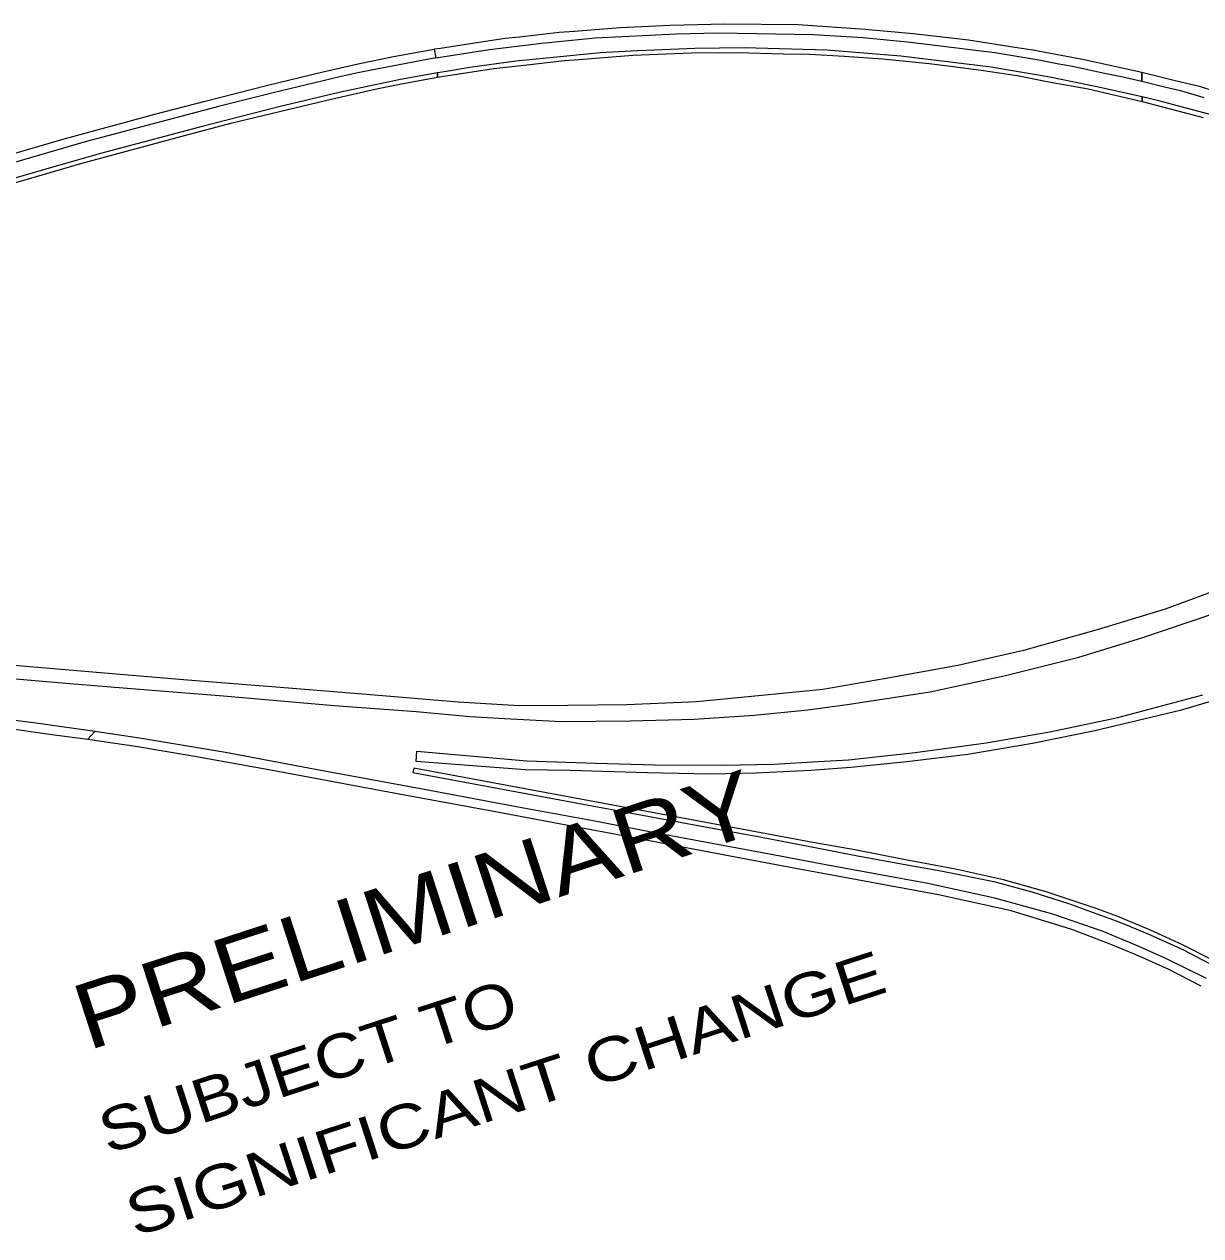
# Model space of a CAD drawing. Extents: x 2355803 to 2371254, y 6970215 to 6985302.
# Drawn here: x 2362590 to 2363679, y 6977121 to 6978242 of the extents above; entities that cross this region are included whole.
import ezdxf

# ---------------------------------------------------------------- set-up
doc = ezdxf.new("R2010")
doc.units = 0
doc.header["$LTSCALE"] = 7.1
doc.layers.add('12', color=7, linetype='Continuous', lineweight=13)
doc.layers.add('5', color=7, linetype='Continuous', lineweight=13)

msp = doc.modelspace()

# ---------------------------------------------------------------- linework, layer by layer
at = {"layer": '12'}
for points in [[(2363624.629, 6978197.498), (2363571.392, 6978209.381), (2363523.829, 6978218.134), (2363507.182, 6978220.687), (2363464.371, 6978227.436), (2363413.032, 6978233.308), (2363368.628, 6978237.458), (2363306.42, 6978241.484), (2363238.311, 6978242.189), (2363187.974, 6978241.153), (2363141.829, 6978238.976), (2363099.505, 6978235.519), (2363085.292, 6978234.446), (2363048.489, 6978230.239), (2363035.277, 6978228.833), (2363009.086, 6978225.094), (2362975.34, 6978219.735), (2362969.629, 6978218.966), (2362971.1, 6978211.141), (2363020.701, 6978218.89), (2363069.298, 6978224.596), (2363118.514, 6978229.587), (2363193.664, 6978233.202), (2363232.268, 6978234.188), (2363268.182, 6978233.646), (2363320.589, 6978232.565), (2363366.688, 6978229.909), (2363410.563, 6978225.707), (2363488.545, 6978215.942), (2363529.465, 6978209.184), (2363546.254, 6978205.766), (2363560.48, 6978203.366), (2363590.269, 6978197.014), (2363607.042, 6978193.523), (2363624.805, 6978189.625)], [(2363624.976, 6978174.991), (2363582.975, 6978184.382), (2363539.557, 6978193.128), (2363485.231, 6978202.456), (2363401.593, 6978212.54), (2363332.987, 6978218.305), (2363256.709, 6978220.424), (2363211.018, 6978219.828), (2363157.725, 6978217.709), (2363123.334, 6978215.629), (2363089.286, 6978212.47), (2363045.305, 6978207.864), (2363002.644, 6978202.096), (2362980.78, 6978198.465), (2362972.709, 6978197.189), (2362972.69, 6978193.077), (2362994.479, 6978196.708), (2363024.697, 6978201.2), (2363058.025, 6978205.058), (2363090.364, 6978208.662), (2363103.38, 6978209.64), (2363153.423, 6978213.644), (2363207.777, 6978215.725), (2363250.035, 6978216.008), (2363293.01, 6978214.936), (2363317.481, 6978214.624), (2363349.278, 6978212.61), (2363384.641, 6978210.293), (2363427.888, 6978205.897), (2363450.034, 6978203.018), (2363475.958, 6978199.616), (2363509.271, 6978194.596), (2363540.103, 6978188.672), (2363574.924, 6978182.425), (2363624.928, 6978170.71)]]:
    msp.add_lwpolyline(points, close=True, dxfattribs=at)
for points in [[(2362564.258, 6978117.891), (2362624.835, 6978135.481), (2362710.835, 6978159.048), (2362757.488, 6978171.135), (2362815.524, 6978185.767), (2362865.278, 6978197.781), (2362900.446, 6978205.836), (2362931.776, 6978212.169), (2362969.629, 6978218.966), (2362971.1, 6978211.141), (2362916.27, 6978200.68), (2362897.259, 6978196.992), (2362882.165, 6978193.498), (2362820.575, 6978178.838), (2362771.184, 6978166.213), (2362646.483, 6978133.232), (2362569.269, 6978110.865)], [(2362565.763, 6978091.095), (2362608.652, 6978103.551), (2362642.395, 6978113.398), (2362738.265, 6978139.302), (2362782.543, 6978150.9), (2362868.919, 6978171.641), (2362916.205, 6978182.531), (2362939.372, 6978186.991), (2362972.69, 6978193.077), (2362972.709, 6978197.189), (2362938.326, 6978191.032), (2362903.087, 6978183.677), (2362878.864, 6978178.297), (2362849.289, 6978171.205), (2362825.83, 6978165.795), (2362754.696, 6978147.593), (2362660.76, 6978122.394), (2362609.956, 6978108.092), (2362557.445, 6978092.824)], [(2363692.731, 6978179.876), (2363679.232, 6978184.094), (2363655.675, 6978189.842), (2363624.629, 6978197.498), (2363624.805, 6978189.625), (2363645.8, 6978184.328), (2363660.668, 6978180.746), (2363682.194, 6978174.357)], [(2363695.886, 6978156.339), (2363639.328, 6978171.62), (2363624.976, 6978174.991), (2363624.928, 6978170.71), (2363681.652, 6978155.806)], [(2363706.611, 6977722.987), (2363646.266, 6977700.933), (2363583.373, 6977681.803), (2363515.068, 6977662.545), (2363454.374, 6977648.76), (2363386.068, 6977636.231), (2363329.492, 6977626.378), (2363272.851, 6977620.926), (2363212.342, 6977615.191), (2363147.995, 6977612.285), (2363093.333, 6977611.645), (2363048.232, 6977611.447), (2362991.618, 6977614.583), (2362910.563, 6977621.436), (2362826.863, 6977628.292), (2362741.205, 6977635.148), (2362660.639, 6977642.001), (2362562.255, 6977650.326)], [(2362542.394, 6977639.613), (2362632.263, 6977632.071), (2362704.56, 6977626.146), (2362774.426, 6977620.591), (2362876.969, 6977611.626), (2362952.771, 6977606.029), (2363003.001, 6977601.385), (2363034.639, 6977599.482), (2363087.555, 6977596.953), (2363150.94, 6977597.446), (2363210.167, 6977598.916), (2363265.967, 6977602.833), (2363315.403, 6977607.73), (2363351.794, 6977612.629), (2363428.857, 6977624.251), (2363497.42, 6977639.083), (2363566.446, 6977656.232), (2363624.817, 6977674.308), (2363689.673, 6977696.092)], [(2363725.621, 6977626.57), (2363660.301, 6977607.104), (2363581.27, 6977588.099), (2363523.363, 6977576.511), (2363463.602, 6977566.315), (2363407.084, 6977559.362), (2363355.228, 6977554.22), (2363318.389, 6977551.409), (2363267.813, 6977548.91), (2363225.355, 6977547.973), (2363166.662, 6977549.222), (2363095.169, 6977551.409), (2363053.912, 6977552.19), (2362952.814, 6977559.66), (2362953.59, 6977569.421), (2363055.288, 6977560.452), (2363119.208, 6977558.28), (2363173.842, 6977556.719), (2363237.218, 6977556.406), (2363284.048, 6977557.343), (2363324.945, 6977559.842), (2363353.043, 6977561.404), (2363414.959, 6977568.169), (2363480.742, 6977576.975), (2363539.577, 6977587.172), (2363602.58, 6977600.613), (2363681.148, 6977621.472)], [(2362572.625, 6977591.105), (2362615.485, 6977584.956), (2362648.934, 6977580.42), (2362655.255, 6977587.643), (2362603.182, 6977594.831), (2362545.384, 6977602.496)], [(2363684.669, 6977358.895), (2363647.003, 6977377.405), (2363621.355, 6977388.894), (2363588.891, 6977402.452), (2363542.429, 6977418.548), (2363488.76, 6977433.337), (2363426.492, 6977446.809), (2363332.046, 6977464.244), (2363285.056, 6977473.059), (2363175.414, 6977493.627), (2363116.677, 6977504.89), (2363055.74, 6977516.15), (2362955.397, 6977534.759), (2362859.658, 6977552.386), (2362776.447, 6977568.057), (2362696.86, 6977581.276), (2362655.255, 6977587.643), (2362648.934, 6977580.42), (2362692.945, 6977573.931), (2362746.1, 6977565.119), (2362820.01, 6977551.896), (2362937.287, 6977529.862), (2363022.945, 6977514.191), (2363085.351, 6977502.442), (2363152.898, 6977489.709), (2363211, 6977478.622), (2363297.665, 6977462.225), (2363436.433, 6977436.862), (2363502.612, 6977422.25), (2363559.512, 6977404.486), (2363593.641, 6977391.76), (2363605.662, 6977386.79), (2363622.114, 6977379.906), (2363649.461, 6977367.487), (2363679.381, 6977352.249)], [(2363687.272, 6977377.53), (2363662.93, 6977389.965), (2363646.953, 6977397.238), (2363632.615, 6977403.722), (2363602.422, 6977416.26), (2363582.559, 6977423.834), (2363536.253, 6977439.277), (2363496.676, 6977450.364), (2363452.349, 6977460.263), (2363405.967, 6977468.948), (2363359.145, 6977477.932), (2363320.02, 6977484.991), (2363272.236, 6977493.654), (2363188.184, 6977509.392), (2362950.662, 6977553.691), (2362949.929, 6977549.759), (2363212.124, 6977500.972), (2363272.557, 6977489.803), (2363323.711, 6977479.998), (2363359.844, 6977472.923), (2363407.307, 6977464.26), (2363438.497, 6977458.679), (2363487.573, 6977448.78), (2363522.797, 6977439.277), (2363556.924, 6977428.412), (2363601.114, 6977412.225), (2363609.663, 6977409.06), (2363632.494, 6977399.435), (2363663.168, 6977385.412), (2363692.131, 6977370.528)]]:
    msp.add_lwpolyline(points, dxfattribs=at)

# ---------------------------------------------------------------- texts
at = {"layer": '5'}
for s, height, width, p in [('PRELIMINARY', 60.55, 1.2, (2362648.55, 6977291.927)), ('SIGNIFICANT CHANGE', 40.37, 1.25, (2362692.287, 6977119.617)), ('SUBJECT TO', 40.37, 1.2, (2362667.363, 6977196.179))]:
    msp.add_text(s, height=height, rotation=18.031, dxfattribs=dict(at, width=width)).set_placement(p)

doc.saveas('drawing.dxf')
